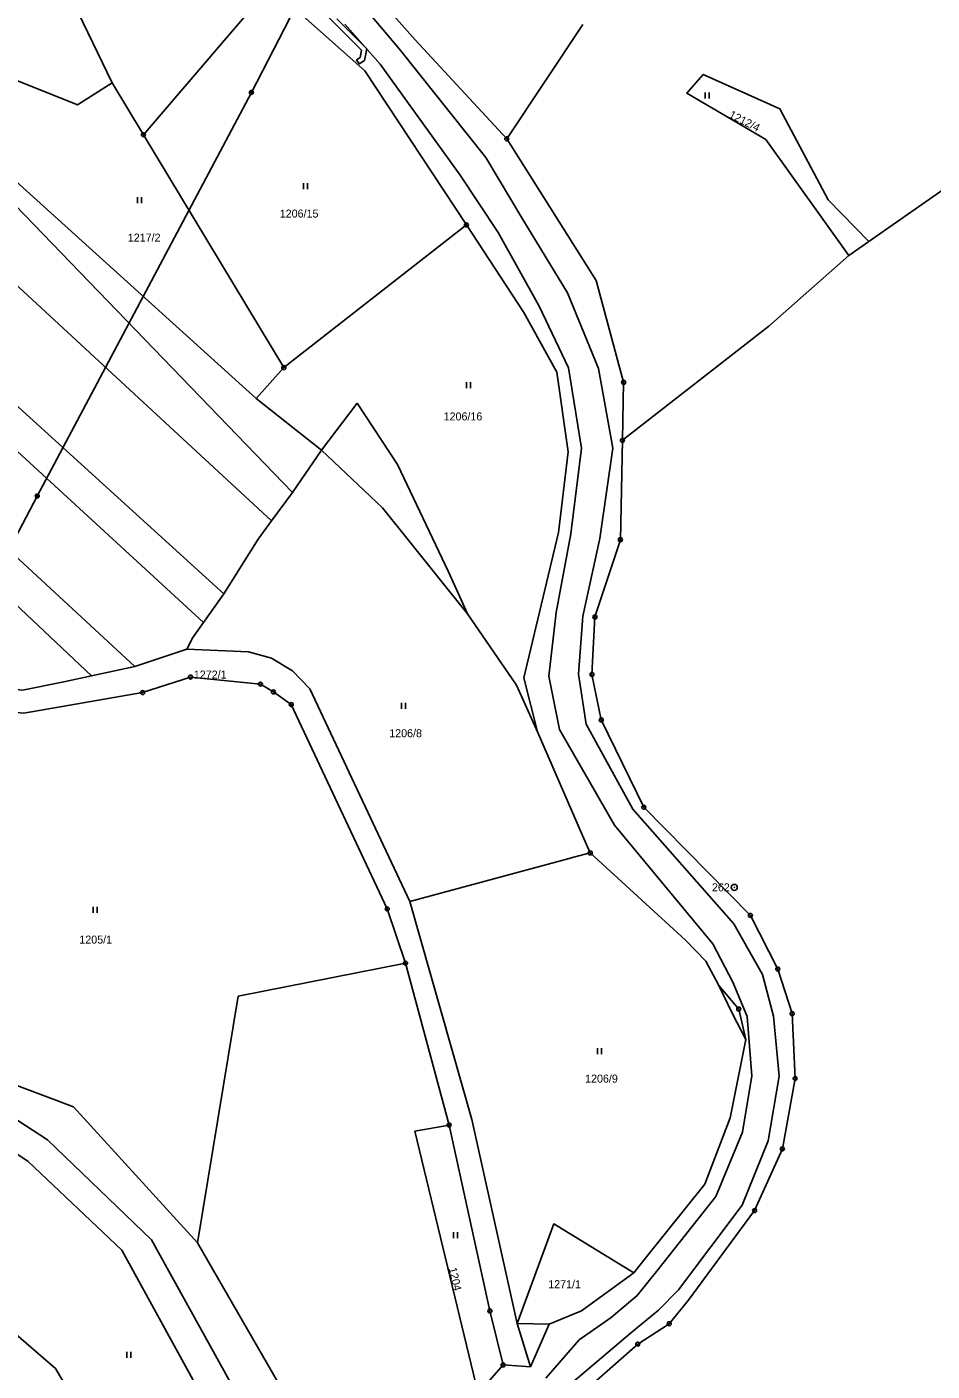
# Model space of a CAD drawing. Extents: x -745926 to -742978, y -968282 to -965689.
# Drawn here: x -745276.5 to -745163.3, y -967417.7 to -967249.8 of the extents above; entities that cross this region are included whole.
import ezdxf

# ---------------------------------------------------------------- set-up
doc = ezdxf.new("R2010")
doc.units = 0
for name, color, linetype in [('Hranice parcel', 7, 'Continuous'), ('Parcelní čísla', 7, 'Continuous'), ('Poz předměty', 7, 'Continuous'), ('Vnitřní kresba', 7, 'Continuous'), ('Věcná břemena k části', 7, 'Continuous'), ('Značky bodu BP', 7, 'Continuous'), ('Značky kultur', 7, 'Continuous')]:
    doc.layers.add(name, color=color, linetype=linetype)

msp = doc.modelspace()

# ---------------------------------------------------------------- linework, layer by layer
at = {"layer": 'Hranice parcel'}
for p, q in [((-745207, -967249.46), (-745216.49, -967263.75)), ((-745305.48, -967256.46), (-745245.9, -967311.49)), ((-745265.83, -967256.76), (-745261.92, -967263.24)), ((-745261.92, -967263.24), (-745244.37, -967292.34)), ((-745316.18, -967267.52), (-745254.4, -967324.19)), ((-745171.21, -967276.58), (-745160.6, -967269.17)), ((-745244.37, -967292.34), (-745221.54, -967274.51)), ((-745171.21, -967276.58), (-745173.73, -967278.34)), ((-745324.31, -967278.33), (-745268.41, -967330.85)), ((-745244.37, -967292.34), (-745247.82, -967296.2)), ((-745239.65, -967302.65), (-745247.82, -967296.2)), ((-745215.18, -967411.81), (-745213.52, -967417.2)), ((-745216.95, -967416.98), (-745220.07, -967420.55)), ((-745213.52, -967417.2), (-745216.95, -967416.98))]:
    msp.add_line(p, q, dxfattribs=at)
for points in [[(-745216.49, -967263.75), (-745227.93, -967251.37), (-745232.64, -967246.06), (-745247.64, -967232.92), (-745257.66, -967225.39), (-745264.18, -967218.33), (-745266.51, -967213.17), (-745267.21, -967207.88), (-745265.62, -967199.33), (-745260.46, -967191.33), (-745259.97, -967189.99)], [(-745292.54, -967223.04), (-745270.72, -967246.67), (-745265.83, -967256.76)], [(-745261.92, -967263.24), (-745260.97, -967262.13), (-745246.09, -967244.71)], [(-745246.09, -967244.71), (-745234.23, -967255.25), (-745221.54, -967274.51)], [(-745247.82, -967296.2), (-745284.44, -967263.18), (-745277.76, -967256.48), (-745270.18, -967259.52), (-745265.83, -967256.76)], [(-745173.73, -967278.34), (-745184.11, -967263.82), (-745194, -967258.06), (-745191.93, -967255.71), (-745182.34, -967260.01), (-745176.33, -967271.37), (-745171.21, -967276.58)], [(-745216.49, -967263.75), (-745205.32, -967281.46), (-745201.88, -967294.17), (-745202.03, -967301.42)], [(-745221.54, -967274.51), (-745214.35, -967285.44), (-745210.25, -967292.91), (-745208.8, -967302.86), (-745210.01, -967312.96), (-745214.37, -967331.1), (-745212.67, -967337.86)], [(-745202.03, -967301.42), (-745183.71, -967287.16), (-745173.73, -967278.34)], [(-745188.07, -967498.46), (-745195.3, -967474.77), (-745209.38, -967455.44), (-745214.45, -967443.3), (-745212.86, -967426.94), (-745207.41, -967420.8), (-745200.11, -967414.37), (-745196.18, -967411.82), (-745193.83, -967408.93), (-745185.5, -967397.68), (-745182.04, -967389.97), (-745180.44, -967381.18), (-745180.81, -967373.07), (-745182.61, -967367.5), (-745186.04, -967360.8), (-745199.36, -967347.28), (-745204.68, -967336.37), (-745205.84, -967330.69), (-745205.47, -967323.5), (-745202.29, -967313.85), (-745202.03, -967301.42)], [(-745245.9, -967311.49), (-745243.28, -967307.95), (-745239.65, -967302.65)], [(-745221.4, -967323.13), (-745232.02, -967309.87), (-745239.65, -967302.65)], [(-745342.87, -967305.11), (-745341.66, -967308.19), (-745314.58, -967334.28), (-745311.79, -967334.53), (-745292.96, -967330.93), (-745277.04, -967332.63), (-745271.88, -967331.6), (-745268.41, -967330.85)], [(-745245.9, -967311.49), (-745247.58, -967313.76), (-745251.86, -967320.62), (-745254.4, -967324.19)], [(-745254.4, -967324.19), (-745255.73, -967326.06), (-745256.51, -967327.53)], [(-745212.67, -967337.86), (-745215.27, -967332.01), (-745221.4, -967323.13)], [(-745268.41, -967330.85), (-745263.02, -967329.68), (-745256.51, -967327.53)], [(-745256.51, -967327.53), (-745248.8, -967327.86), (-745245.92, -967328.65), (-745243.29, -967330.22), (-745241.11, -967332.48), (-745228.61, -967359.04)], [(-745315.12, -967338.37), (-745311.55, -967337.64), (-745295.97, -967334.63), (-745292.57, -967334.12), (-745276.86, -967335.52), (-745262.03, -967332.95), (-745256.05, -967331.01), (-745247.29, -967331.89), (-745245.67, -967332.87), (-745243.44, -967334.45), (-745231.44, -967359.98), (-745229.15, -967366.77), (-745223.7, -967386.99)], [(-745212.67, -967337.86), (-745207.01, -967350.8), (-745206.05, -967352.99)], [(-745242.16, -967435.08), (-745243.92, -967421.19), (-745255.18, -967401.72), (-745270.69, -967384.71), (-745284.55, -967379.5), (-745296.85, -967366.21), (-745306.77, -967358.21), (-745321.05, -967346.4)], [(-745323.69, -967349.98), (-745316.18, -967358.65), (-745312.89, -967362.47), (-745307.1, -967369.65), (-745303.29, -967371.65), (-745300.75, -967373.18), (-745292.97, -967375.75), (-745287.25, -967380.29), (-745281.39, -967384.02), (-745273.92, -967388.83), (-745260.93, -967401.35), (-745248.64, -967423.53), (-745242.16, -967435.08)], [(-745228.61, -967359.04), (-745208.68, -967353.69), (-745208.28, -967353.58), (-745206.05, -967352.99)], [(-745206.05, -967352.99), (-745194.13, -967363.88), (-745191.61, -967366.53), (-745189.96, -967369.56), (-745187.5, -967372.5), (-745186.6, -967376.3), (-745188.57, -967386.11), (-745191.74, -967394.4), (-745199.19, -967403.66), (-745200.59, -967405.45)], [(-745228.61, -967359.04), (-745220.85, -967386.29), (-745215.18, -967411.81)], [(-745241.32, -967443.39), (-745252.19, -967425.23), (-745264.62, -967402.64), (-745276.34, -967391.56), (-745283.49, -967386.77), (-745289.1, -967382.97), (-745294.27, -967378.56), (-745302.78, -967376.25), (-745305.28, -967375.21)], [(-745223.7, -967386.99), (-745228, -967387.76), (-745220.07, -967420.55)], [(-745216.95, -967416.98), (-745218.61, -967410.23), (-745223.7, -967386.99)], [(-745302.82, -967391.87), (-745289.96, -967402.7), (-745272.94, -967417.41), (-745260.12, -967438.9), (-745257.81, -967461.8)], [(-745215.18, -967411.81), (-745210.62, -967399.36), (-745200.59, -967405.45)], [(-745200.59, -967405.45), (-745207.14, -967410.2), (-745211.18, -967411.86), (-745213.52, -967417.2)]]:
    msp.add_lwpolyline(points, dxfattribs=at)
at = {"layer": 'Poz předměty'}
for p, q in [((-745248.43, -967257.95), (-745225.94, -967214.52)), ((-745275.21, -967308.39), (-745248.43, -967257.95)), ((-745305.32, -967365.67), (-745275.21, -967308.39))]:
    msp.add_line(p, q, dxfattribs=at)
for centre, radius in [((-745248.43, -967257.95), 0.25), ((-745248.43, -967257.95), 0.2), ((-745248.43, -967257.95), 0.15), ((-745248.43, -967257.95), 0.1), ((-745248.43, -967257.95), 0.05), ((-745275.21, -967308.39), 0.25), ((-745275.21, -967308.39), 0.2), ((-745275.21, -967308.39), 0.15), ((-745275.21, -967308.39), 0.1), ((-745275.21, -967308.39), 0.05)]:
    msp.add_circle(centre, radius, dxfattribs=at)
at = {"layer": 'Vnitřní kresba'}
for p, q in [((-745233.99, -967247.73), (-745229.89, -967252.56)), ((-745243.28, -967307.95), (-745299.23, -967250.06)), ((-745232.33, -967254.41), (-745236.74, -967249.4)), ((-745229.89, -967252.56), (-745219.12, -967266.07)), ((-745222.31, -967268.27), (-745232.33, -967254.41)), ((-745251.86, -967320.62), (-745313.52, -967264.69)), ((-745219.12, -967266.07), (-745214.49, -967273.82)), ((-745217.56, -967275.46), (-745222.31, -967268.27)), ((-745214.49, -967273.82), (-745208.9, -967282.98)), ((-745263.02, -967329.68), (-745322, -967275.16)), ((-745212.45, -967284.68), (-745217.56, -967275.46)), ((-745208.9, -967282.98), (-745205.01, -967292.45)), ((-745208.77, -967292.37), (-745212.45, -967284.68)), ((-745207.17, -967302.4), (-745208.77, -967292.37)), ((-745205.01, -967292.45), (-745203.24, -967302.41)), ((-745239.65, -967302.65), (-745235.19, -967296.77)), ((-745235.19, -967296.77), (-745230.15, -967304.46)), ((-745208.49, -967313.13), (-745207.17, -967302.4)), ((-745203.24, -967302.41), (-745204.84, -967313.69)), ((-745230.15, -967304.46), (-745223.78, -967317.85)), ((-745210.32, -967322.95), (-745208.49, -967313.13)), ((-745204.84, -967313.69), (-745206.98, -967323.4)), ((-745223.78, -967317.85), (-745221.4, -967323.13)), ((-745211.23, -967330.9), (-745210.32, -967322.95)), ((-745206.98, -967323.4), (-745207.53, -967330.66)), ((-745209.89, -967337.56), (-745211.23, -967330.9)), ((-745207.53, -967330.66), (-745206.56, -967336.89)), ((-745203.04, -967349.53), (-745209.89, -967337.56)), ((-745206.56, -967336.89), (-745200.74, -967347.52)), ((-745200.74, -967347.52), (-745188.11, -967361.86)), ((-745190.75, -967364.34), (-745203.04, -967349.53)), ((-745188.11, -967361.86), (-745184.5, -967368.18)), ((-745188.25, -967369.15), (-745190.75, -967364.34)), ((-745250.09, -967370.88), (-745229.15, -967366.77)), ((-745188.3, -967373), (-745189.96, -967369.56)), ((-745186.44, -967373.43), (-745188.25, -967369.15)), ((-745184.5, -967368.18), (-745183.15, -967373.4)), ((-745255.18, -967401.72), (-745250.09, -967370.88)), ((-745186.6, -967376.3), (-745188.3, -967373)), ((-745185.87, -967380.83), (-745186.44, -967373.43)), ((-745183.15, -967373.4), (-745182.43, -967380.89)), ((-745187.04, -967387.89), (-745185.87, -967380.83)), ((-745182.43, -967380.89), (-745183.82, -967388.98)), ((-745190.36, -967395.93), (-745187.04, -967387.89)), ((-745183.82, -967388.98), (-745187.06, -967397.02)), ((-745197.77, -967405.31), (-745190.36, -967395.93)), ((-745187.06, -967397.02), (-745195.03, -967407.57)), ((-745200.2, -967408.28), (-745197.77, -967405.31)), ((-745203.43, -967411.04), (-745200.2, -967408.28)), ((-745195.03, -967407.57), (-745197.52, -967410.13)), ((-745197.52, -967410.13), (-745201.07, -967413.03)), ((-745211.18, -967411.86), (-745215.18, -967411.81)), ((-745207.45, -967413.82), (-745203.43, -967411.04)), ((-745201.07, -967413.03), (-745209.04, -967419.81)), ((-745211.6, -967418.61), (-745207.45, -967413.82))]:
    msp.add_line(p, q, dxfattribs=at)
at = {"layer": 'Věcná břemena k části'}
for points in [[(-745267.71, -967203.61), (-745268.31, -967208.18), (-745268.4, -967209.76), (-745266.95, -967214.83), (-745271.3, -967217.82), (-745272.04, -967218.41), (-745271.58, -967219.19), (-745268.85, -967222.17), (-745266.31, -967224.94), (-745260.9, -967230.38), (-745256.53, -967233.25), (-745252.81, -967236.46), (-745247.35, -967240.57), (-745242.72, -967244.67), (-745238.15, -967249.17), (-745234.64, -967252.69), (-745234.83, -967253.58), (-745235.28, -967253.88), (-745234.94, -967254.38), (-745234.29, -967253.94), (-745233.98, -967252.49)], [(-745233.98, -967252.49), (-745237.73, -967248.75)]]:
    msp.add_lwpolyline(points, dxfattribs=at)
at = {"layer": 'Značky bodu BP'}
for centre, radius in [((-745261.92, -967263.24), 0.25), ((-745261.92, -967263.24), 0.0152), ((-745216.49, -967263.75), 0.25), ((-745216.49, -967263.75), 0.0152), ((-745221.54, -967274.51), 0.25), ((-745221.54, -967274.51), 0.0152), ((-745244.37, -967292.34), 0.25), ((-745244.37, -967292.34), 0.0152), ((-745201.88, -967294.17), 0.25), ((-745201.88, -967294.17), 0.0152), ((-745202.03, -967301.42), 0.25), ((-745202.03, -967301.42), 0.0152), ((-745202.29, -967313.85), 0.25), ((-745202.29, -967313.85), 0.0152), ((-745205.47, -967323.5), 0.25), ((-745205.47, -967323.5), 0.0152), ((-745256.05, -967331.01), 0.25), ((-745256.05, -967331.01), 0.0152), ((-745205.84, -967330.69), 0.25), ((-745205.84, -967330.69), 0.0152), ((-745262.03, -967332.95), 0.25), ((-745247.29, -967331.89), 0.25), ((-745247.29, -967331.89), 0.0152), ((-745245.67, -967332.87), 0.25), ((-745245.67, -967332.87), 0.0152), ((-745262.03, -967332.95), 0.0152), ((-745243.44, -967334.45), 0.25), ((-745243.44, -967334.45), 0.0152), ((-745204.68, -967336.37), 0.25), ((-745204.68, -967336.37), 0.0152), ((-745199.36, -967347.28), 0.25), ((-745199.36, -967347.28), 0.0152), ((-745206.05, -967352.99), 0.25), ((-745206.05, -967352.99), 0.0152), ((-745188.05, -967357.29), 0.375), ((-745188.05, -967357.29), 0.015), ((-745231.44, -967359.98), 0.25), ((-745231.44, -967359.98), 0.0152), ((-745186.04, -967360.8), 0.25), ((-745186.04, -967360.8), 0.0152), ((-745229.15, -967366.77), 0.25), ((-745229.15, -967366.77), 0.0152), ((-745182.61, -967367.5), 0.25), ((-745182.61, -967367.5), 0.0152), ((-745187.5, -967372.5), 0.25), ((-745187.5, -967372.5), 0.0152), ((-745180.81, -967373.07), 0.25), ((-745180.81, -967373.07), 0.0152), ((-745180.44, -967381.18), 0.25), ((-745180.44, -967381.18), 0.0152), ((-745223.7, -967386.99), 0.25), ((-745223.7, -967386.99), 0.0152), ((-745182.04, -967389.97), 0.25), ((-745182.04, -967389.97), 0.0152), ((-745185.5, -967397.68), 0.25), ((-745185.5, -967397.68), 0.0152), ((-745218.61, -967410.23), 0.25), ((-745218.61, -967410.23), 0.0152), ((-745196.18, -967411.82), 0.25), ((-745196.18, -967411.82), 0.0152), ((-745200.11, -967414.37), 0.25), ((-745200.11, -967414.37), 0.0152), ((-745216.95, -967416.98), 0.25), ((-745216.95, -967416.98), 0.0152)]:
    msp.add_circle(centre, radius, dxfattribs=at)
at = {"layer": 'Značky kultur'}
for p, q in [((-745191.67, -967258.71), (-745191.67, -967257.96)), ((-745191.17, -967258.71), (-745191.17, -967257.96)), ((-745241.92, -967270.06), (-745241.92, -967269.31)), ((-745241.42, -967270.06), (-745241.42, -967269.31)), ((-745262.68, -967271.81), (-745262.68, -967271.06)), ((-745262.18, -967271.81), (-745262.18, -967271.06)), ((-745221.55, -967294.89), (-745221.55, -967294.14)), ((-745221.05, -967294.89), (-745221.05, -967294.14)), ((-745229.64, -967334.98), (-745229.64, -967334.23)), ((-745229.14, -967334.98), (-745229.14, -967334.23)), ((-745268.22, -967360.48), (-745268.22, -967359.73)), ((-745267.71, -967360.48), (-745267.71, -967359.73)), ((-745205.15, -967378.14), (-745205.15, -967377.39)), ((-745204.65, -967378.14), (-745204.65, -967377.39)), ((-745223.16, -967401.12), (-745223.16, -967400.37)), ((-745222.66, -967401.12), (-745222.66, -967400.37)), ((-745264, -967416.09), (-745264, -967415.34)), ((-745263.49, -967416.09), (-745263.49, -967415.34))]:
    msp.add_line(p, q, dxfattribs=at)

# ---------------------------------------------------------------- texts
at = {"layer": 'Parcelní čísla'}
for s, rotation, p in [('1212/4', 333, (-745188.81, -967261.05)), ('1204', 283, (-745223.76, -967404.9))]:
    msp.add_text(s, height=1, rotation=rotation, dxfattribs=at).set_placement(p)
for s, p in [('1206/15', (-745244.88, -967273.59)), ('1217/2', (-745263.88, -967276.59)), ('1206/16', (-745224.39, -967298.94)), ('1272/1', (-745255.62, -967331.2)), ('1206/8', (-745231.19, -967338.53)), ('1205/1', (-745269.94, -967364.32)), ('1206/9', (-745206.7, -967381.69)), ('1271/1', (-745211.31, -967407.38))]:
    msp.add_text(s, height=1, dxfattribs=at).set_placement(p)
at = {"layer": 'Značky bodu BP'}
msp.add_text('262', height=1, dxfattribs=at).set_placement((-745190.84, -967357.79))

doc.saveas('drawing.dxf')
